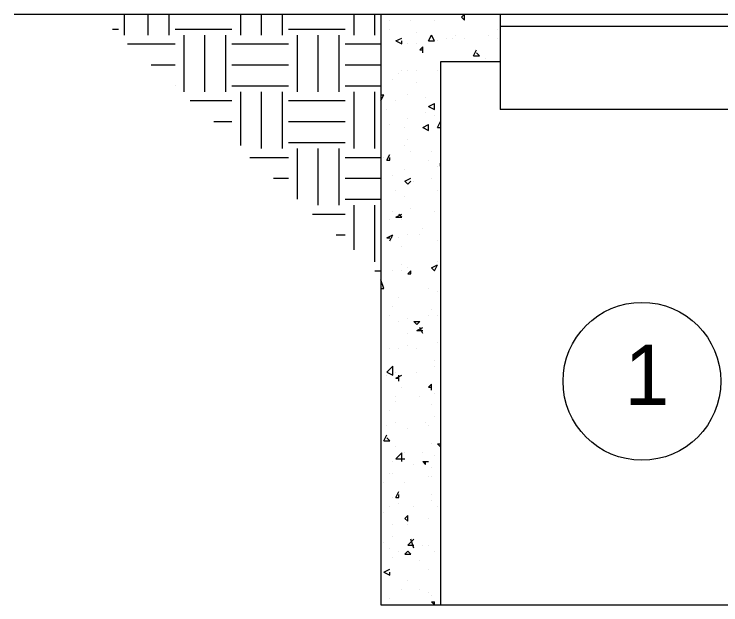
# Model space of a CAD drawing. Extents: x -119017 to -116080, y -104449 to -102845.
# Drawn here: x -116614.3 to -116532.1, y -103356.8 to -103288.1 of the extents above; entities that cross this region are included whole.
import ezdxf

# ---------------------------------------------------------------- set-up
doc = ezdxf.new("R2010")
doc.units = 0
doc.layers.add('G-MARK', color=7, linetype='Continuous')
doc.layers.add('Misc CnstDet(22)', color=7, linetype='Continuous')

msp = doc.modelspace()

# ---------------------------------------------------------------- linework, layer by layer
at = {"layer": 'G-MARK'}
msp.add_circle((-116541.26, -103330.768), 9.184, dxfattribs=at)
at = {"layer": 'Misc CnstDet(22)'}
for p, q in [((-116614.329, -103288.052), (-116319.302, -103288.052)), ((-116601.487, -103290.481), (-116601.487, -103288.052)), ((-116598.71, -103290.481), (-116598.71, -103288.052)), ((-116596.28, -103290.481), (-116596.28, -103288.052)), ((-116587.95, -103290.481), (-116587.95, -103288.052)), ((-116585.521, -103290.481), (-116585.521, -103288.052)), ((-116583.091, -103290.481), (-116583.091, -103288.052)), ((-116574.761, -103290.481), (-116574.761, -103288.052)), ((-116572.331, -103290.481), (-116572.331, -103288.052)), ((-116571.637, -103288.052), (-116571.637, -103356.776)), ((-116562.266, -103288.399), (-116561.918, -103288.052)), ((-116561.918, -103288.746), (-116561.918, -103288.052)), ((-116557.753, -103288.052), (-116557.753, -103299.159)), ((-116570.596, -103288.746), (-116570.596, -103288.746)), ((-116568.166, -103288.746), (-116568.166, -103288.746)), ((-116565.389, -103288.746), (-116565.389, -103288.746)), ((-116562.266, -103288.399), (-116561.918, -103288.746)), ((-116602.875, -103289.787), (-116602.181, -103289.787)), ((-116595.586, -103289.787), (-116588.992, -103289.787)), ((-116582.397, -103289.787), (-116575.802, -103289.787)), ((-116570.596, -103289.787), (-116570.596, -103289.787)), ((-116558.1, -103289.787), (-116558.1, -103289.787)), ((-116557.753, -103289.44), (-116468.204, -103289.44)), ((-116594.545, -103297.076), (-116594.545, -103290.481)), ((-116592.115, -103297.076), (-116592.115, -103290.481)), ((-116589.686, -103297.076), (-116589.686, -103290.481)), ((-116581.356, -103297.076), (-116581.356, -103290.481)), ((-116578.926, -103297.076), (-116578.926, -103290.481)), ((-116576.496, -103297.076), (-116576.496, -103290.481)), ((-116567.472, -103290.134), (-116567.472, -103290.134)), ((-116566.084, -103291.176), (-116565.736, -103290.481)), ((-116565.389, -103291.176), (-116565.736, -103290.481)), ((-116562.96, -103290.481), (-116562.96, -103290.481)), ((-116559.142, -103290.481), (-116559.142, -103290.481)), ((-116601.14, -103291.523), (-116595.586, -103291.523)), ((-116588.992, -103291.523), (-116582.397, -103291.523)), ((-116575.802, -103291.523), (-116571.637, -103291.523)), ((-116569.902, -103291.176), (-116569.207, -103290.828)), ((-116569.902, -103291.176), (-116569.207, -103291.523)), ((-116569.207, -103291.523), (-116569.207, -103291.176)), ((-116568.513, -103291.523), (-116568.513, -103291.523)), ((-116568.513, -103291.523), (-116568.513, -103291.523)), ((-116567.472, -103291.523), (-116567.472, -103291.523)), ((-116566.084, -103291.176), (-116565.389, -103291.176)), ((-116565.042, -103291.176), (-116565.042, -103291.176)), ((-116564.001, -103290.828), (-116564.001, -103290.828)), ((-116563.307, -103290.828), (-116563.307, -103290.828)), ((-116561.918, -103290.828), (-116561.918, -103290.828)), ((-116558.1, -103290.828), (-116558.1, -103290.828)), ((-116567.125, -103292.217), (-116566.778, -103291.87)), ((-116567.125, -103292.217), (-116566.778, -103292.217)), ((-116566.778, -103292.564), (-116566.778, -103291.87)), ((-116560.877, -103292.911), (-116560.53, -103292.217)), ((-116560.877, -103292.911), (-116560.183, -103292.911)), ((-116560.183, -103292.911), (-116560.53, -103292.564)), ((-116598.363, -103293.952), (-116595.586, -103293.952)), ((-116588.992, -103293.952), (-116582.397, -103293.952)), ((-116575.802, -103293.952), (-116571.637, -103293.952)), ((-116564.695, -103293.605), (-116564.695, -103356.776)), ((-116557.753, -103293.605), (-116564.695, -103293.605)), ((-116559.489, -103293.258), (-116559.489, -103293.258)), ((-116558.448, -103293.605), (-116558.448, -103293.605)), ((-116569.207, -103294.646), (-116569.207, -103294.646)), ((-116568.513, -103294.646), (-116568.513, -103294.646)), ((-116567.472, -103294.646), (-116567.472, -103294.646)), ((-116565.042, -103294.646), (-116565.042, -103294.646)), ((-116569.554, -103294.994), (-116569.554, -103294.994)), ((-116595.586, -103296.382), (-116595.586, -103296.382)), ((-116588.992, -103296.382), (-116582.397, -103296.382)), ((-116575.802, -103296.382), (-116571.637, -103296.382)), ((-116570.249, -103295.688), (-116570.249, -103295.688)), ((-116567.472, -103296.035), (-116567.472, -103296.035)), ((-116587.95, -103303.324), (-116587.95, -103297.076)), ((-116585.521, -103303.671), (-116585.521, -103297.076)), ((-116583.091, -103303.671), (-116583.091, -103297.076)), ((-116574.761, -103303.671), (-116574.761, -103297.076)), ((-116572.331, -103303.671), (-116572.331, -103297.076)), ((-116593.851, -103298.117), (-116588.992, -103298.117)), ((-116582.397, -103298.117), (-116575.802, -103298.117)), ((-116571.637, -103298.117), (-116571.29, -103297.423)), ((-116571.637, -103297.423), (-116571.29, -103297.423)), ((-116571.637, -103297.77), (-116571.637, -103297.77)), ((-116569.902, -103298.117), (-116569.902, -103298.117)), ((-116568.513, -103297.423), (-116568.513, -103297.423)), ((-116566.431, -103297.77), (-116566.431, -103297.77)), ((-116566.084, -103298.812), (-116565.389, -103298.464)), ((-116566.084, -103298.812), (-116565.389, -103299.159)), ((-116565.389, -103299.159), (-116565.389, -103298.464)), ((-116570.943, -103299.159), (-116570.943, -103299.159)), ((-116566.431, -103299.506), (-116566.431, -103299.506)), ((-116468.204, -103299.159), (-116557.753, -103299.159)), ((-116591.074, -103300.547), (-116588.992, -103300.547)), ((-116582.397, -103300.547), (-116575.802, -103300.547)), ((-116568.513, -103300.2), (-116568.513, -103300.2)), ((-116565.389, -103299.853), (-116565.389, -103299.853)), ((-116565.042, -103301.241), (-116564.695, -103300.547)), ((-116570.596, -103300.894), (-116570.596, -103300.894)), ((-116568.86, -103301.241), (-116568.86, -103301.241)), ((-116566.778, -103301.241), (-116566.084, -103300.894)), ((-116566.778, -103301.241), (-116566.084, -103301.588)), ((-116566.084, -103301.588), (-116566.084, -103300.894)), ((-116565.042, -103301.241), (-116564.695, -103301.241)), ((-116582.397, -103302.977), (-116575.802, -103302.977)), ((-116568.513, -103302.63), (-116568.513, -103302.63)), ((-116581.356, -103309.571), (-116581.356, -103303.671)), ((-116578.926, -103310.266), (-116578.926, -103303.671)), ((-116576.496, -103310.266), (-116576.496, -103303.671)), ((-116568.86, -103303.324), (-116568.86, -103303.324)), ((-116586.909, -103304.712), (-116582.397, -103304.712)), ((-116575.802, -103304.712), (-116571.637, -103304.712)), ((-116571.29, -103304.712), (-116571.29, -103304.712)), ((-116570.943, -103305.059), (-116570.596, -103304.365)), ((-116570.596, -103305.059), (-116570.596, -103304.712)), ((-116568.166, -103304.018), (-116568.166, -103304.018)), ((-116565.736, -103304.018), (-116565.736, -103304.018)), ((-116570.943, -103305.059), (-116570.943, -103305.059)), ((-116570.943, -103305.059), (-116570.596, -103305.059)), ((-116566.084, -103305.059), (-116566.084, -103305.059)), ((-116564.695, -103305.753), (-116564.695, -103305.406)), ((-116568.86, -103306.1), (-116568.86, -103306.1)), ((-116565.042, -103305.753), (-116565.042, -103305.753)), ((-116564.695, -103305.753), (-116564.695, -103305.753)), ((-116584.132, -103307.142), (-116582.397, -103307.142)), ((-116575.802, -103307.142), (-116571.637, -103307.142)), ((-116570.249, -103306.795), (-116570.249, -103306.795)), ((-116568.86, -103307.489), (-116568.166, -103307.142)), ((-116565.736, -103307.142), (-116565.736, -103307.142)), ((-116568.86, -103307.489), (-116568.513, -103307.836)), ((-116568.513, -103307.836), (-116568.166, -103307.489)), ((-116567.819, -103307.489), (-116567.819, -103307.489)), ((-116569.902, -103308.53), (-116569.902, -103308.53)), ((-116565.042, -103308.53), (-116565.042, -103308.53)), ((-116575.802, -103309.571), (-116571.637, -103309.571)), ((-116568.86, -103309.224), (-116568.86, -103309.224)), ((-116574.761, -103315.472), (-116574.761, -103310.266)), ((-116572.331, -103316.86), (-116572.331, -103310.266)), ((-116570.249, -103310.96), (-116570.249, -103310.96)), ((-116568.166, -103310.613), (-116568.166, -103310.613)), ((-116565.389, -103310.96), (-116565.389, -103310.96)), ((-116579.62, -103311.307), (-116575.802, -103311.307)), ((-116570.596, -103312.001), (-116570.596, -103312.001)), ((-116569.902, -103311.654), (-116569.207, -103311.307)), ((-116569.902, -103311.654), (-116569.207, -103311.654)), ((-116569.207, -103311.654), (-116569.554, -103311.307)), ((-116569.207, -103312.001), (-116569.207, -103312.001)), ((-116576.843, -103313.736), (-116575.802, -103313.736)), ((-116570.943, -103314.084), (-116570.249, -103313.736)), ((-116570.596, -103314.431), (-116570.249, -103313.736)), ((-116568.513, -103313.736), (-116568.513, -103313.736)), ((-116567.125, -103313.736), (-116567.125, -103313.736)), ((-116566.778, -103313.042), (-116566.778, -103313.042)), ((-116570.943, -103314.084), (-116570.596, -103314.084)), ((-116570.249, -103314.084), (-116570.249, -103314.084)), ((-116569.554, -103314.084), (-116569.554, -103314.084)), ((-116565.042, -103314.431), (-116565.042, -103314.431)), ((-116564.695, -103314.431), (-116564.695, -103314.431)), ((-116569.207, -103315.125), (-116569.207, -103315.125)), ((-116565.042, -103316.86), (-116565.042, -103316.86)), ((-116569.207, -103317.207), (-116569.207, -103317.207)), ((-116568.513, -103317.554), (-116568.513, -103317.554)), ((-116565.736, -103317.554), (-116565.042, -103317.207)), ((-116565.736, -103317.554), (-116565.389, -103317.902)), ((-116565.389, -103317.902), (-116565.042, -103317.207)), ((-116564.695, -103317.554), (-116564.695, -103317.554)), ((-116572.331, -103317.902), (-116571.637, -103317.902)), ((-116570.249, -103317.902), (-116570.249, -103317.902)), ((-116569.207, -103317.902), (-116569.207, -103317.902)), ((-116568.513, -103318.249), (-116568.166, -103317.902)), ((-116568.513, -103318.249), (-116568.166, -103318.249)), ((-116568.166, -103318.249), (-116568.166, -103317.902)), ((-116571.29, -103319.984), (-116571.637, -103318.943)), ((-116571.637, -103318.943), (-116571.637, -103318.943)), ((-116571.637, -103319.984), (-116571.29, -103319.984)), ((-116566.084, -103319.984), (-116566.084, -103319.984)), ((-116565.042, -103320.331), (-116565.042, -103320.331)), ((-116569.554, -103321.025), (-116569.554, -103321.025)), ((-116570.249, -103322.067), (-116570.249, -103322.067)), ((-116565.736, -103322.414), (-116565.736, -103322.414)), ((-116565.736, -103322.414), (-116565.736, -103322.414)), ((-116570.596, -103323.108), (-116570.596, -103323.108)), ((-116568.513, -103323.455), (-116568.513, -103323.455)), ((-116568.513, -103323.455), (-116568.513, -103323.455)), ((-116566.084, -103323.108), (-116566.084, -103323.108)), ((-116565.042, -103323.108), (-116565.042, -103323.108)), ((-116569.554, -103323.802), (-116569.554, -103323.802)), ((-116567.819, -103323.802), (-116567.472, -103324.149)), ((-116567.819, -103323.802), (-116567.125, -103323.802)), ((-116567.472, -103324.149), (-116567.125, -103323.802)), ((-116568.513, -103325.19), (-116568.513, -103325.19)), ((-116567.472, -103324.843), (-116566.778, -103324.496)), ((-116567.472, -103324.843), (-116566.778, -103324.843)), ((-116566.778, -103325.19), (-116567.125, -103324.496)), ((-116568.513, -103326.579), (-116568.513, -103326.579)), ((-116565.042, -103326.232), (-116565.042, -103326.232)), ((-116565.042, -103326.232), (-116565.042, -103326.232)), ((-116570.596, -103326.926), (-116570.596, -103326.926)), ((-116569.554, -103326.926), (-116569.554, -103326.926)), ((-116567.472, -103326.926), (-116567.472, -103326.926)), ((-116565.389, -103328.314), (-116565.389, -103328.314)), ((-116570.943, -103329.703), (-116570.249, -103329.008)), ((-116570.249, -103329.008), (-116570.249, -103329.008)), ((-116570.249, -103330.05), (-116570.249, -103329.008)), ((-116565.389, -103329.008), (-116565.389, -103329.008)), ((-116570.943, -103329.703), (-116570.249, -103330.05)), ((-116570.943, -103330.05), (-116570.943, -103330.05)), ((-116569.902, -103329.703), (-116569.902, -103329.703)), ((-116569.902, -103330.397), (-116569.207, -103330.05)), ((-116569.554, -103330.744), (-116569.554, -103330.05)), ((-116567.472, -103329.703), (-116567.472, -103329.703)), ((-116569.902, -103330.397), (-116569.554, -103330.397)), ((-116569.207, -103331.438), (-116569.207, -103331.438)), ((-116566.084, -103331.438), (-116565.736, -103331.091)), ((-116566.084, -103331.438), (-116565.736, -103331.438)), ((-116565.736, -103331.785), (-116565.736, -103331.091)), ((-116569.902, -103332.479), (-116569.902, -103332.479)), ((-116567.125, -103332.479), (-116567.125, -103332.479)), ((-116565.389, -103332.132), (-116565.389, -103332.132)), ((-116569.902, -103333.174), (-116569.902, -103333.174)), ((-116570.596, -103334.215), (-116570.596, -103334.215)), ((-116565.736, -103333.521), (-116565.736, -103333.521)), ((-116564.695, -103333.868), (-116564.695, -103333.868)), ((-116564.695, -103333.868), (-116564.695, -103333.868)), ((-116565.389, -103334.909), (-116565.389, -103334.909)), ((-116570.943, -103335.95), (-116570.943, -103335.95)), ((-116569.902, -103335.603), (-116569.902, -103335.603)), ((-116566.431, -103335.603), (-116566.431, -103335.603)), ((-116566.084, -103335.95), (-116566.084, -103335.95)), ((-116571.637, -103336.297), (-116571.637, -103336.297)), ((-116571.637, -103336.644), (-116571.637, -103336.644)), ((-116568.513, -103336.297), (-116568.513, -103336.297)), ((-116571.29, -103337.686), (-116570.943, -103336.992)), ((-116570.596, -103337.686), (-116570.943, -103337.339)), ((-116571.29, -103337.686), (-116570.596, -103337.686)), ((-116569.902, -103338.38), (-116569.902, -103338.38)), ((-116565.736, -103338.033), (-116565.736, -103338.033)), ((-116565.042, -103338.033), (-116564.695, -103338.38)), ((-116565.042, -103338.033), (-116564.695, -103338.033)), ((-116569.902, -103339.768), (-116569.207, -103339.074)), ((-116569.207, -103340.115), (-116569.207, -103339.074)), ((-116568.86, -103339.074), (-116568.86, -103339.074)), ((-116566.778, -103339.074), (-116566.778, -103339.074)), ((-116569.902, -103339.768), (-116568.86, -103339.768)), ((-116565.389, -103339.421), (-116565.389, -103339.421)), ((-116570.249, -103340.115), (-116570.249, -103340.115)), ((-116567.819, -103340.462), (-116567.819, -103340.462)), ((-116566.778, -103340.115), (-116566.431, -103340.462)), ((-116566.778, -103340.115), (-116566.084, -103340.115)), ((-116566.431, -103340.462), (-116566.431, -103340.115)), ((-116565.736, -103340.81), (-116565.736, -103340.81)), ((-116570.596, -103341.504), (-116570.596, -103341.504)), ((-116570.249, -103341.504), (-116570.249, -103341.504)), ((-116571.29, -103342.545), (-116571.29, -103342.545)), ((-116568.86, -103342.545), (-116568.86, -103342.545)), ((-116566.084, -103341.851), (-116566.084, -103341.851)), ((-116565.736, -103341.851), (-116565.736, -103341.851)), ((-116569.902, -103344.28), (-116569.554, -103343.586)), ((-116569.554, -103344.28), (-116569.554, -103343.933)), ((-116565.736, -103343.933), (-116565.736, -103343.933)), ((-116570.249, -103344.28), (-116570.249, -103344.28)), ((-116569.902, -103344.28), (-116569.554, -103344.28)), ((-116569.554, -103344.975), (-116569.554, -103344.975)), ((-116565.736, -103344.628), (-116565.736, -103344.628)), ((-116570.596, -103345.322), (-116570.596, -103345.322)), ((-116567.819, -103345.322), (-116567.819, -103345.322)), ((-116565.042, -103345.322), (-116565.042, -103345.322)), ((-116571.29, -103346.016), (-116571.29, -103346.016)), ((-116568.86, -103346.71), (-116568.513, -103346.363)), ((-116568.513, -103347.057), (-116568.513, -103346.363)), ((-116570.249, -103347.404), (-116570.249, -103347.404)), ((-116568.86, -103346.71), (-116568.513, -103347.057)), ((-116568.513, -103347.404), (-116568.513, -103347.404)), ((-116566.084, -103346.71), (-116566.084, -103346.71)), ((-116564.695, -103348.099), (-116564.695, -103348.099)), ((-116570.249, -103348.793), (-116570.249, -103348.793)), ((-116571.29, -103349.487), (-116571.29, -103349.487)), ((-116568.513, -103349.834), (-116567.819, -103349.14)), ((-116568.513, -103349.834), (-116567.819, -103349.834)), ((-116567.819, -103350.181), (-116568.166, -103349.14)), ((-116566.778, -103349.834), (-116566.778, -103349.834)), ((-116566.084, -103349.834), (-116566.084, -103349.834)), ((-116570.596, -103350.181), (-116570.596, -103350.181)), ((-116569.554, -103350.528), (-116569.554, -103350.528)), ((-116568.86, -103350.875), (-116568.513, -103350.528)), ((-116568.166, -103350.875), (-116568.513, -103350.528)), ((-116565.389, -103350.528), (-116565.389, -103350.528)), ((-116570.249, -103351.222), (-116570.249, -103351.222)), ((-116568.86, -103350.875), (-116568.166, -103350.875)), ((-116567.125, -103351.569), (-116567.125, -103351.569)), ((-116564.695, -103350.875), (-116564.695, -103350.875)), ((-116564.695, -103351.222), (-116564.695, -103351.222)), ((-116571.29, -103352.958), (-116570.596, -103352.611)), ((-116571.29, -103352.958), (-116570.596, -103353.305)), ((-116570.596, -103353.305), (-116570.596, -103352.958)), ((-116566.084, -103352.611), (-116566.084, -103352.611)), ((-116570.596, -103353.305), (-116570.596, -103353.305)), ((-116568.513, -103353.999), (-116568.513, -103353.999)), ((-116569.207, -103355.04), (-116569.207, -103355.04)), ((-116567.125, -103355.04), (-116567.125, -103355.04)), ((-116566.084, -103355.387), (-116566.084, -103355.387)), ((-116570.596, -103356.082), (-116570.596, -103356.082)), ((-116565.736, -103355.735), (-116565.736, -103355.735)), ((-116565.736, -103356.429), (-116565.389, -103356.776)), ((-116565.736, -103356.429), (-116565.389, -103356.429)), ((-116565.389, -103356.776), (-116565.389, -103356.429)), ((-116571.637, -103356.776), (-116454.32, -103356.776)), ((-116570.943, -103356.776), (-116570.943, -103356.776))]:
    msp.add_line(p, q, dxfattribs=at)

# ---------------------------------------------------------------- texts
msp.add_text('1', height=7, dxfattribs=at).set_placement((-116543.286, -103333.522))

doc.saveas('drawing.dxf')
